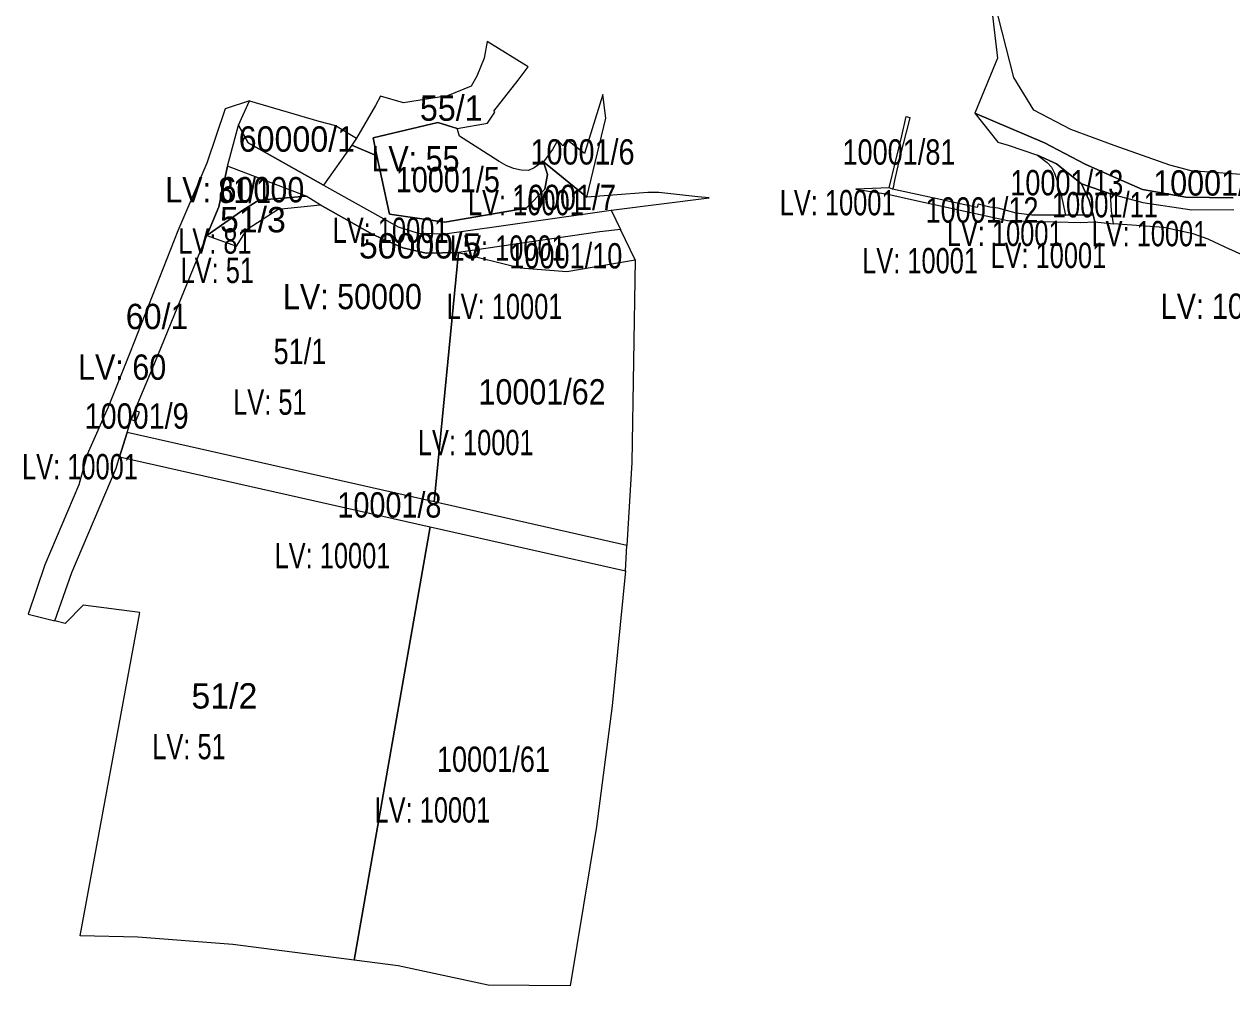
# Model space of a CAD drawing. Extents: x -713758 to -711119, y -1123067 to -1120789.
# Drawn here: x -712311.1 to -711834.3, y -1123066.8 to -1122687.3 of the extents above; entities that cross this region are included whole.
import ezdxf
from ezdxf.enums import TextEntityAlignment as Align

# ---------------------------------------------------------------- set-up
doc = ezdxf.new("R2010")
doc.units = 0
doc.header["$LTSCALE"] = 4
doc.layers.add('10', color=7, linetype='Continuous', lineweight=13)
doc.layers.add('11', color=7, linetype='Continuous')
doc.layers.add('13', color=7, linetype='Continuous')

msp = doc.modelspace()

# ---------------------------------------------------------------- linework, layer by layer
at = {"layer": '10'}
for points in [[(-711825.18, -1122746.95), (-711850.37, -1122745.1), (-711858.79, -1122742.93), (-711880.82, -1122735.21), (-711897.89, -1122728.87), (-711912.45, -1122721.22), (-711920.37, -1122708.38), (-711931.14, -1122665.93), (-711975.15, -1122645.71), (-711966.02, -1122627.33), (-711947.94, -1122594.74), (-711934.86, -1122567.27), (-711932.45, -1122568.1), (-711914.97, -1122541.31), (-711898.41, -1122515.73), (-711721.48, -1122522.77)], [(-711825.18, -1122746.95), (-711850.37, -1122745.1), (-711858.79, -1122742.93), (-711880.82, -1122735.21), (-711897.89, -1122728.87), (-711912.45, -1122721.22), (-711920.37, -1122708.38), (-711931.14, -1122665.93), (-711975.15, -1122645.71), (-711974.63, -1122649.6), (-711933.42, -1122665.59), (-711935.68, -1122671.26), (-711930.08, -1122672.58), (-711926.82, -1122700.64), (-711935.71, -1122722.45), (-711908.21, -1122734.05), (-711892.24, -1122742.54), (-711882.27, -1122747.05), (-711869.63, -1122752.59), (-711852.47, -1122755.55), (-711833.73, -1122755.85)], [(-711833.73, -1122755.85), (-711852.47, -1122755.55), (-711869.63, -1122752.59), (-711882.27, -1122747.05), (-711892.24, -1122742.54), (-711908.21, -1122734.05), (-711935.71, -1122722.45), (-711926.63, -1122733.86), (-711922.59, -1122735.07), (-711910.97, -1122739), (-711903.52, -1122742.35), (-711893.72, -1122750.3), (-711882.16, -1122754.3), (-711869.43, -1122757.72), (-711850.1, -1122760.54), (-711833.51, -1122760.45)], [(-711823.99, -1122781.13), (-711836.65, -1122775.48), (-711843.58, -1122772.18), (-711849.63, -1122770.02), (-711861.1, -1122767.55), (-711880.99, -1122766.12), (-711881.8, -1122760.94), (-711882.16, -1122754.3), (-711869.43, -1122757.72), (-711850.1, -1122760.54), (-711833.51, -1122760.45)]]:
    msp.add_lwpolyline(points, dxfattribs=at)
for points in [[(-712181.8, -1122735.02), (-712171.87, -1122739.18), (-712173.38, -1122732.19), (-712147.84, -1122726.02), (-712140.22, -1122728.43), (-712128.19, -1122726.34), (-712125.31, -1122722), (-712125.7, -1122721.66), (-712116.13, -1122709.33), (-712112.11, -1122704.13), (-712128.26, -1122694.12), (-712129.48, -1122700.7), (-712132.38, -1122707.77), (-712134.61, -1122711.68), (-712143.93, -1122715.58), (-712161.32, -1122718.36), (-712170.39, -1122715.7), (-712172.46, -1122719.37), (-712179.9, -1122732.33)], [(-712106.14, -1122741.61), (-712089, -1122755.49), (-712081.44, -1122724.31), (-712082.63, -1122715.08), (-712089.88, -1122738.37), (-712096.91, -1122732.87), (-712098.5, -1122735.24), (-712100.41, -1122733.02), (-712102.51, -1122736.7)], [(-712309.56, -1122920.06), (-712298.97, -1122922.73), (-712292.26, -1122903.73), (-712274.86, -1122862.44), (-712273.51, -1122857.97), (-712270.47, -1122848.41), (-712268.83, -1122843.27), (-712267.41, -1122839.7), (-712259.57, -1122820.88), (-712238.99, -1122770.7), (-712234.26, -1122759.37), (-712230.87, -1122743.36), (-712226.52, -1122727.07), (-712222.14, -1122717.55), (-712231.71, -1122720.68), (-712238.98, -1122742.07), (-712250.47, -1122768.88), (-712269.22, -1122816.75), (-712278.02, -1122838.46), (-712285.68, -1122855.95), (-712286.32, -1122857.14), (-712289.59, -1122869.07), (-712302.92, -1122900.71)], [(-712226.52, -1122727.07), (-712222.14, -1122717.55), (-712194.82, -1122725.58), (-712188.23, -1122727.3), (-712179.9, -1122732.33), (-712181.8, -1122735.02), (-712192.96, -1122750.79), (-712222.69, -1122734.17)], [(-711969.55, -1122751.82), (-711964.6, -1122731.33), (-711962.93, -1122723.7), (-711961.43, -1122724.1), (-711961.76, -1122725.35), (-711965.2, -1122739.05), (-711967.49, -1122748.99), (-711968.07, -1122751.7), (-711968.22, -1122752.45)], [(-712230.87, -1122743.36), (-712226.52, -1122727.07), (-712222.69, -1122734.17), (-712192.96, -1122750.79), (-712163.46, -1122767.28), (-712155.6, -1122769.71), (-712144.97, -1122770.04), (-712079.39, -1122760.68), (-712075.65, -1122768.34), (-712083.88, -1122769.18), (-712139.66, -1122777.43), (-712152.34, -1122777.65), (-712161.65, -1122775.57), (-712173.47, -1122770.26), (-712194.32, -1122758.57), (-712199.73, -1122755.09)], [(-712173.38, -1122732.19), (-712171.87, -1122739.18), (-712166.86, -1122762.28), (-712145, -1122765.38), (-712112.92, -1122759.86), (-712105.49, -1122752.35), (-712104.53, -1122746.62), (-712106.14, -1122741.61), (-712106.59, -1122741.31), (-712107.16, -1122742.19), (-712109.7, -1122744.03), (-712111.97, -1122745.09), (-712114.85, -1122744.9), (-712117.9, -1122744.25), (-712120.83, -1122743.07), (-712123.56, -1122741.43), (-712139.28, -1122731.52), (-712140.22, -1122728.43), (-712147.84, -1122726.02)], [(-712192.96, -1122750.79), (-712163.46, -1122767.28), (-712155.6, -1122769.71), (-712144.97, -1122770.04), (-712079.39, -1122760.68), (-712040.67, -1122755.8), (-712045.18, -1122755.48), (-712060.52, -1122753.74), (-712064.94, -1122753.76), (-712078.76, -1122754.75), (-712089, -1122755.49), (-712106.14, -1122741.61), (-712104.53, -1122746.62), (-712105.49, -1122752.35), (-712112.92, -1122759.86), (-712145, -1122765.38), (-712166.86, -1122762.28), (-712171.87, -1122739.18), (-712181.8, -1122735.02)], [(-711910.97, -1122739), (-711907.24, -1122741.84), (-711905.49, -1122743.77), (-711904.26, -1122746.11), (-711903.15, -1122749.51), (-711902.94, -1122751.15), (-711901.88, -1122754.07), (-711900.02, -1122762.62), (-711889.1, -1122762.47), (-711890.58, -1122756.91), (-711893.72, -1122750.3), (-711903.52, -1122742.35)], [(-712238.99, -1122770.7), (-712224.83, -1122760.67), (-712218.54, -1122756.69), (-712199.73, -1122755.09), (-712230.87, -1122743.36), (-712234.26, -1122759.37)], [(-711982.71, -1122752.33), (-711970.17, -1122754.37), (-711959.58, -1122756.69), (-711922.9, -1122764.71), (-711894, -1122765.52), (-711888.35, -1122765.3), (-711889.1, -1122762.47), (-711900.02, -1122762.62), (-711905.71, -1122762.69), (-711908.18, -1122762.7), (-711913.28, -1122762.61), (-711918.37, -1122762.02), (-711919.46, -1122761.83), (-711926.54, -1122759.89), (-711929.89, -1122759.54), (-711934.45, -1122758.26), (-711934.88, -1122759.57), (-711968.22, -1122752.45), (-711969.55, -1122751.82)], [(-711893.72, -1122750.3), (-711890.58, -1122756.91), (-711889.1, -1122762.47), (-711888.35, -1122765.3), (-711880.99, -1122766.12), (-711881.8, -1122760.94), (-711882.16, -1122754.3)], [(-712238.99, -1122770.7), (-712227.34, -1122774.89), (-712223.1, -1122768.24), (-712210.81, -1122760.3), (-712194.32, -1122758.57), (-712199.73, -1122755.09), (-712218.54, -1122756.69), (-712224.83, -1122760.67)], [(-712270.47, -1122848.41), (-712268.83, -1122843.27), (-712267.05, -1122843.99), (-712265.65, -1122840.37), (-712267.41, -1122839.7), (-712259.57, -1122820.88), (-712238.99, -1122770.7), (-712227.34, -1122774.89), (-712223.1, -1122768.24), (-712210.81, -1122760.3), (-712194.32, -1122758.57), (-712173.47, -1122770.26), (-712161.65, -1122775.57), (-712152.34, -1122777.65), (-712139.66, -1122777.43), (-712149.19, -1122875.79)], [(-712139.66, -1122777.43), (-712115.23, -1122783.45), (-712096.8, -1122784.88), (-712069.85, -1122780.23), (-712075.65, -1122768.34), (-712083.88, -1122769.18)], [(-712149.19, -1122875.79), (-712139.66, -1122777.43), (-712115.23, -1122783.45), (-712096.8, -1122784.88), (-712069.85, -1122780.23), (-712071.18, -1122860.29), (-712073.11, -1122892.96)], [(-712268.83, -1122843.27), (-712267.05, -1122843.99), (-712265.65, -1122840.37), (-712267.41, -1122839.7)], [(-712273.51, -1122857.97), (-712150.84, -1122885.67), (-712073.71, -1122903.08), (-712073.11, -1122892.96), (-712149.19, -1122875.79), (-712270.47, -1122848.41)], [(-712298.97, -1122922.73), (-712292.26, -1122903.73), (-712274.86, -1122862.44), (-712273.51, -1122857.97), (-712150.84, -1122885.67), (-712180.81, -1123056.65), (-712228.71, -1123050.53), (-712266.23, -1123047.6), (-712288.97, -1123047.01), (-712265.43, -1122919.45), (-712287.86, -1122916.56), (-712294.9, -1122923.75)], [(-712180.81, -1123056.65), (-712150.84, -1122885.67), (-712073.71, -1122903.08), (-712078.96, -1122956.27), (-712085.09, -1123003.92), (-712095.5, -1123066.8), (-712127.99, -1123066.59), (-712163.52, -1123058.86)]]:
    msp.add_lwpolyline(points, close=True, dxfattribs=at)

# ---------------------------------------------------------------- texts
at = {"layer": '11'}
for s, width, p in [('55/1', 0.95, (-712142.51, -1122725.4)), ('60000/1', 0.95, (-712203.45, -1122737.6)), ('10001/6', 0.85, (-712090.671, -1122742.68)), ('10001/81', 0.8, (-711965.721, -1122742.72)), ('10001/5', 0.85, (-712143.85, -1122753.6)), ('81/1', 0.8, (-712224.04, -1122757.85)), ('10001/13', 0.8, (-711899.47, -1122754.84)), ('10001/23', 0.9, (-711840.231, -1122754.94)), ('10001/7', 0.85, (-712098, -1122760.65)), ('10001/11', 0.75, (-711884.41, -1122763.52)), ('10001/12', 0.8, (-711932.94, -1122765.61)), ('10001/10', 0.8, (-712097.27, -1122783.69)), ('60/1', 0.95, (-712258.66, -1122807.63)), ('51/1', 0.8, (-712202.24, -1122821.44)), ('10001/62', 0.9, (-712106.64, -1122837.38)), ('10001/9', 0.85, (-712266.721, -1122846.91)), ('10001/8', 0.85, (-712166.92, -1122882)), ('10001/61', 0.8, (-712125.851, -1122982.37))]:
    msp.add_text(s, height=10, dxfattribs=dict(at, width=width)).set_placement(p, align=Align.CENTER)
for s, p in [('51/3', (-712220.819, -1122769.43)), ('50000/5', (-712154.79, -1122779.76)), ('51/2', (-712232.071, -1122957.37))]:
    msp.add_text(s, height=10, dxfattribs=at).set_placement(p, align=Align.CENTER)
at = {"layer": '13'}
for s, width, p in [('LV: 55 ', 0.9, (-712154.958, -1122745.4)), ('LV: 60000 ', 0.9, (-712226.302, -1122757.6)), ('LV: 10001 ', 0.75, (-712111.65, -1122762.68)), ('LV: 10001 ', 0.75, (-711988.54, -1122762.72)), ('LV: 81 ', 0.75, (-712234.412, -1122777.85)), ('LV: 10001 ', 0.75, (-712165.064, -1122773.6)), ('LV: 10001 ', 0.75, (-711922.591, -1122774.84)), ('LV: 10001 ', 0.75, (-711865.46, -1122774.94)), ('LV: 10001 ', 0.75, (-712118.778, -1122780.65)), ('LV: 10001 ', 0.75, (-711955.994, -1122785.61)), ('LV: 10001 ', 0.75, (-711905.356, -1122783.52)), ('LV: 51 ', 0.75, (-712233.468, -1122789.43)), ('LV: 50000 ', 0.9, (-712179.852, -1122799.76)), ('LV: 10001 ', 0.75, (-712120.09, -1122803.69)), ('LV: 10002 ', 0.85, (-711834.874, -1122803.57)), ('LV: 60 ', 0.9, (-712270.772, -1122827.63)), ('LV: 51 ', 0.75, (-712212.713, -1122841.44)), ('LV: 10001 ', 0.75, (-712131.434, -1122857.38)), ('LV: 10001 ', 0.75, (-712287.7, -1122866.91)), ('LV: 10001 ', 0.75, (-712188, -1122902)), ('LV: 51 ', 0.75, (-712244.652, -1122977.37)), ('LV: 10001 ', 0.75, (-712148.536, -1123002.37))]:
    msp.add_text(s, height=10, dxfattribs=dict(at, width=width)).set_placement(p, align=Align.CENTER)

doc.saveas('drawing.dxf')
